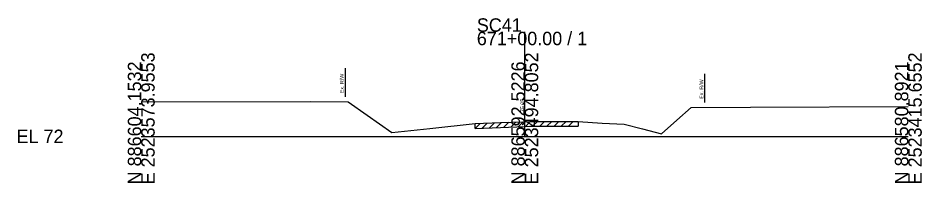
# Model space of a CAD drawing. Extents: x -26 to 183, y -10 to 24021.
# Drawn here: x -25.7 to 162.8, y 3490.3 to 3524.6 of the extents above; entities that cross this region are included whole.
import ezdxf

# ---------------------------------------------------------------- set-up
doc = ezdxf.new("R2010")
doc.units = 0
for name, color, linetype in [('RD_GPK_XS_Cell', 7, 'Continuous'), ('RD_XS_ExGround', 7, 'Continuous'), ('RD_XS_ExPaveRet', 7, 'Continuous'), ('RD_XS_ExRW', 7, 'Continuous'), ('RD_XS_TX_Elev_EX', 7, 'Continuous')]:
    doc.layers.add(name, color=color, linetype=linetype)

msp = doc.modelspace()

# ---------------------------------------------------------------- linework, layer by layer
at = {"layer": 'RD_GPK_XS_Cell'}
for p, q in [((80, 3500), (80, 3521.78)), ((0, 3500), (80, 3500)), ((80, 3500), (160, 3500))]:
    msp.add_line(p, q, dxfattribs=at)
at = {"layer": 'RD_XS_ExGround'}
for p, q in [((0, 3507.2), (35.33, 3507.26)), ((35.33, 3507.26), (43.15, 3507.2)), ((43.15, 3507.2), (47.13, 3504.41)), ((111.7, 3503.35), (114.71, 3506.03)), ((114.71, 3506.03), (127.11, 3506.1)), ((127.11, 3506.1), (160, 3506.21)), ((47.13, 3504.41), (52.29, 3500.77)), ((74.94, 3502.86), (80, 3503.05)), ((80, 3503.05), (81.02, 3503.09)), ((81.02, 3503.09), (85.83, 3503.09)), ((85.83, 3503.09), (91.14, 3503.09)), ((91.14, 3503.09), (96.13, 3502.78)), ((108.52, 3500.55), (111.7, 3503.35)), ((52.29, 3500.77), (60.19, 3501.61)), ((60.19, 3501.61), (69.62, 3502.66)), ((69.62, 3502.66), (74.94, 3502.86)), ((96.13, 3502.78), (100.7, 3502.54)), ((100.7, 3502.54), (104.53, 3501.55)), ((104.53, 3501.55), (108.52, 3500.55))]:
    msp.add_line(p, q, dxfattribs=at)
at = {"layer": 'RD_XS_ExPaveRet'}
for p, q in [((77.12, 3501.94), (78.16, 3502.98)), ((78.62, 3502), (79.66, 3503.04)), ((80.12, 3502.05), (81.15, 3503.09)), ((81.62, 3502.09), (82.62, 3503.09)), ((83.12, 3502.09), (84.12, 3503.09)), ((84.62, 3502.09), (85.62, 3503.09)), ((86.12, 3502.09), (87.12, 3503.09)), ((87.62, 3502.09), (88.62, 3503.09)), ((89.12, 3502.09), (90.12, 3503.09)), ((91.14, 3503.09), (91.14, 3502.09)), ((69.62, 3501.66), (70.66, 3502.7)), ((69.62, 3501.66), (69.62, 3502.66)), ((69.62, 3501.66), (74.94, 3501.86)), ((71.12, 3501.72), (72.16, 3502.76)), ((72.62, 3501.77), (73.66, 3502.81)), ((74.12, 3501.83), (75.16, 3502.87)), ((74.94, 3501.86), (80, 3502.05)), ((75.62, 3501.88), (76.66, 3502.92)), ((80, 3502.05), (81.02, 3502.09)), ((81.02, 3502.09), (85.83, 3502.09)), ((85.83, 3502.09), (91.14, 3502.09))]:
    msp.add_line(p, q, dxfattribs=at)
at = {"layer": 'RD_XS_ExRW'}
for p, q in [((42.5, 3514.2), (42.5, 3508.2)), ((117.5, 3513.05), (117.5, 3507.05))]:
    msp.add_line(p, q, dxfattribs=at)

# ---------------------------------------------------------------- texts
at = {"layer": 'RD_GPK_XS_Cell'}
for s, p in [('SC41', (70, 3521.78)), ('671+00.00 / 1', (70, 3518.98)), ('EL 72', (-26, 3498.6))]:
    msp.add_text(s, height=2.8, dxfattribs=at).set_placement(p)
for s, p in [('E 2523573.9553', (2.8, 3490)), ('E 2523494.8052', (82.8, 3490)), ('E 2523415.6552', (162.8, 3490)), ('N 886604.1532', (0, 3490)), ('N 886592.5226', (80, 3490)), ('N 886580.8921', (160, 3490))]:
    msp.add_text(s, height=2.8, rotation=90, dxfattribs=at).set_placement(p)
at = {"layer": 'RD_XS_ExRW'}
for p in [(42.25, 3508.99), (117.25, 3507.83)]:
    msp.add_text('Ex. R/W ', height=0.8, rotation=90, dxfattribs=at).set_placement(p)
at = {"layer": 'RD_XS_TX_Elev_EX'}
msp.add_text('75.05', height=0.8, rotation=90, dxfattribs=at).set_placement((79.9, 3505.05))

doc.saveas('drawing.dxf')
